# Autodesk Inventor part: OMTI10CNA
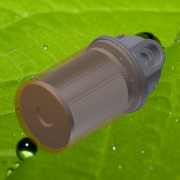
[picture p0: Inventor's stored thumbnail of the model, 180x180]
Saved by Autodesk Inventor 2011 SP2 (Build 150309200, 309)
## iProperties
Created: 2013-12
Part Number: OMTI10CNA
Material: Сталь
Document SubType Name: Modeling
Designer: dorohin
Mass: 3589.54 g
Surface Area: 7410.17 cm^2
Volume: 457.266 cm^3
Density: 7.85 g/cm^3
Author: dorohin
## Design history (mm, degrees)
derived "OMTI.iam"
node "Твердое тело1"
node "None.ipt:1"
node "None_1.ipt:1"
feature "Производный составной элемент1"
